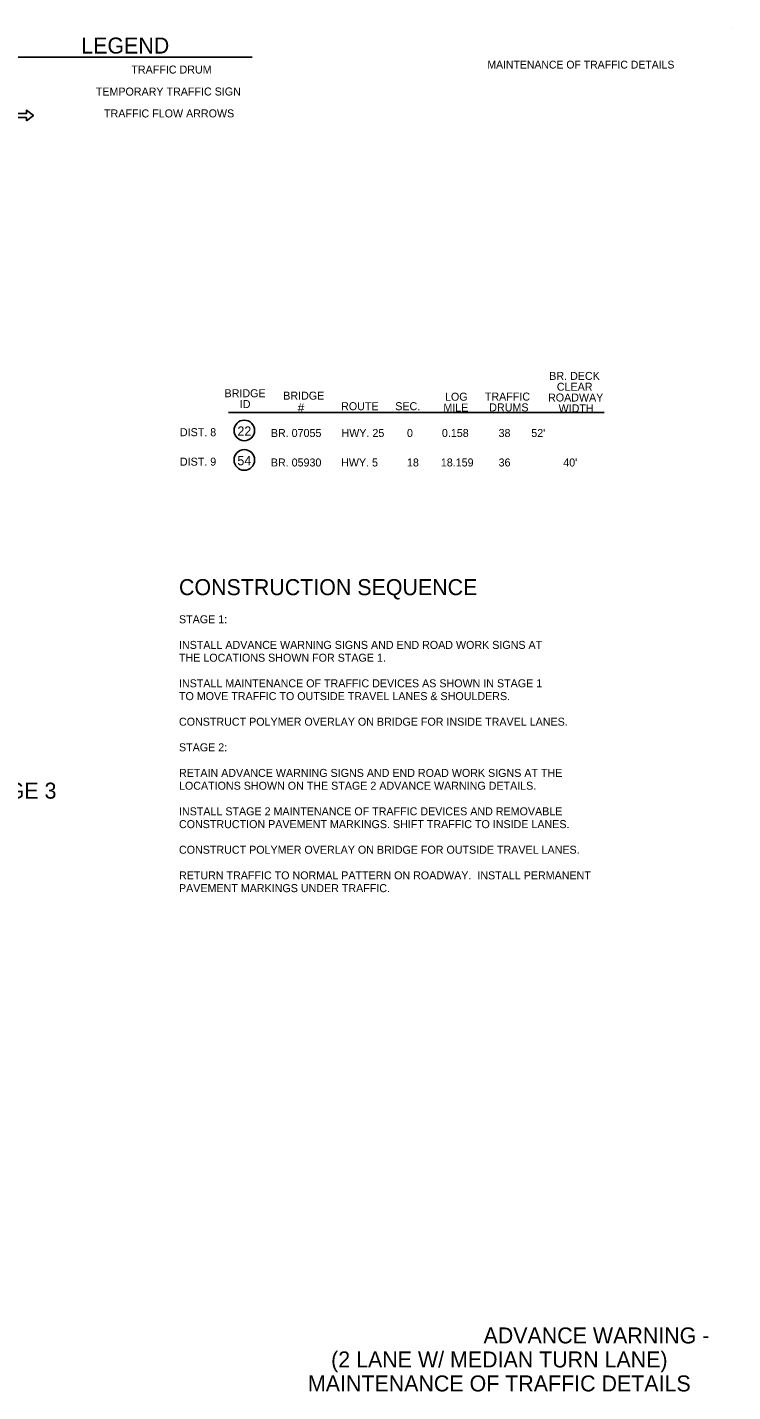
# Model space of a CAD drawing. Extents: x 1930579 to 1946213, y 596452 to 597784.
# Drawn here: x 1937455 to 1937984, y 596607 to 597630 of the extents above; entities that cross this region are included whole.
import ezdxf

# ---------------------------------------------------------------- set-up
doc = ezdxf.new("R2010")
doc.units = 0
for name, color, linetype in [('Default', 7, 'Continuous'), ('R_Border', 7, 'Continuous'), ('R_MOT', 7, 'Continuous'), ('S_AREA_CALC', 7, 'Continuous')]:
    doc.layers.add(name, color=color, linetype=linetype)

msp = doc.modelspace()

# ---------------------------------------------------------------- linework, layer by layer
at = {"layer": 'Default'}
for centre in [(1937617.7, 597327.6), (1937617.7, 597305.5)]:
    msp.add_circle(centre, 7.71, dxfattribs=at)
at = {"layer": 'R_Border'}
for p, q in [((1937429.7, 597607.5), (1937623.6, 597607.6)), ((1937605.9, 597341), (1937887.6, 597341))]:
    msp.add_line(p, q, dxfattribs=at)
at = {"layer": 'R_MOT'}
msp.add_lwpolyline([(1937454.3, 597559.7), (1937459.5, 597563.7), (1937454.3, 597567.7), (1937454.3, 597565.2), (1937439.6, 597565.2), (1937439.6, 597562.2), (1937454.3, 597562.2)], close=True, dxfattribs=at)
at = {"layer": 'S_AREA_CALC'}
msp.add_line((1937984, 597629.9), (1937984, 597629.9), dxfattribs=at)

# ---------------------------------------------------------------- texts
at = {"layer": 'Default'}
msp.add_text('MIRROR LAYOUT FOR STAGE 3', height=12, dxfattribs=at).set_placement((1937232.5, 597051.5))
at = {"layer": 'R_Border'}
for s, height, rotation, p in [('LEGEND', 12, 0.0388, (1937495.4, 597610.2)), ('TRAFFIC DRUM', 6, 0.0388, (1937533, 597595.2)), ('TEMPORARY TRAFFIC SIGN', 6, 0.0388, (1937506.3, 597578.7)), ('TRAFFIC FLOW ARROWS', 6, 0.0388, (1937512.5, 597562.3)), ('BR. DECK ', 6, 360, (1937846.4, 597365.5)), ('CLEAR', 6, 360, (1937852.1, 597357.4)), ('BRIDGE ', 6, 360, (1937602.9, 597352.5)), ('ID', 6, 360, (1937614.3, 597344.4)), ('BRIDGE ', 6, 360, (1937646.9, 597350.7)), ('LOG', 6, 360, (1937768.2, 597349.9)), ('TRAFFIC ', 6, 360, (1937798.1, 597350)), ('ROADWAY ', 6, 360, (1937845.5, 597349.3)), ('#', 6.71, 360, (1937657.7, 597341.3)), ('ROUTE', 6, 360, (1937690.3, 597342.8)), ('SEC.', 6, 360, (1937730.9, 597342.8)), ('MILE', 6, 360, (1937767, 597341.8)), ('DRUMS', 6, 360, (1937801.4, 597341.9)), ('WIDTH', 6, 360, (1937853.4, 597341.2)), ('22', 7, 360, (1937612.5, 597323.6)), ('DIST. 8', 6, 360, (1937569.4, 597323.3)), ('BR. 07055', 6, 360, (1937637.6, 597322.7)), ('HWY. 25', 6, 360, (1937690.6, 597322.7)), ('0', 6, 360, (1937739.7, 597322.7)), ('0.158', 6, 360, (1937765.9, 597322.7)), ("38       52'", 6, 360, (1937808.4, 597322.7)), ('DIST. 9', 6, 360, (1937569.4, 597301.2)), ('54', 7, 360, (1937612.5, 597301.5)), ('BR. 05930', 6, 360, (1937637.6, 597300.6)), ('HWY. 5', 6, 360, (1937690.3, 597300.6)), ('18', 6, 360, (1937739.7, 597300.6)), ('18.159', 6, 360, (1937765.1, 597300.6)), ('36      ', 6, 360, (1937808.4, 597300.6)), ("40'      ", 6, 360, (1937856.9, 597300.6)), ('CONSTRUCTION SEQUENCE', 12, 360, (1937568.7, 597204.1)), ('STAGE 1:', 6, 360, (1937568.7, 597183)), ('INSTALL ADVANCE WARNING SIGNS AND END ROAD WORK SIGNS AT', 6, 360, (1937568.7, 597163.8)), ('THE LOCATIONS SHOWN FOR STAGE 1.', 6, 360, (1937568.7, 597154.2)), ('INSTALL MAINTENANCE OF TRAFFIC DEVICES AS SHOWN IN STAGE 1', 6, 360, (1937568.7, 597135)), ('TO MOVE TRAFFIC TO OUTSIDE TRAVEL LANES & SHOULDERS.', 6, 360, (1937568.7, 597125.4)), ('CONSTRUCT POLYMER OVERLAY ON BRIDGE FOR INSIDE TRAVEL LANES.', 6, 360, (1937568.7, 597106.2)), ('STAGE 2:', 6, 360, (1937568.7, 597087)), ('RETAIN ADVANCE WARNING SIGNS AND END ROAD WORK SIGNS AT THE', 6, 360, (1937568.7, 597067.8)), ('LOCATIONS SHOWN ON THE STAGE 2 ADVANCE WARNING DETAILS.', 6, 360, (1937568.7, 597058.2)), ('INSTALL STAGE 2 MAINTENANCE OF TRAFFIC DEVICES AND REMOVABLE', 6, 360, (1937568.7, 597039)), ('CONSTRUCTION PAVEMENT MARKINGS. SHIFT TRAFFIC TO INSIDE LANES.', 6, 360, (1937568.7, 597029.4)), ('CONSTRUCT POLYMER OVERLAY ON BRIDGE FOR OUTSIDE TRAVEL LANES.', 6, 360, (1937568.7, 597010.2)), ('RETURN TRAFFIC TO NORMAL PATTERN ON ROADWAY.  INSTALL PERMANENT', 6, 360, (1937568.7, 596991)), ('PAVEMENT MARKINGS UNDER TRAFFIC.', 6, 360, (1937568.7, 596981.4)), ('ADVANCE WARNING -', 12, 360, (1937797.1, 596643)), ('(2 LANE W/ MEDIAN TURN LANE)', 12, 360, (1937682.8, 596625)), ('MAINTENANCE OF TRAFFIC DETAILS', 12, 360, (1937665.4, 596607))]:
    msp.add_text(s, height=height, rotation=rotation, dxfattribs=at).set_placement(p)
at = {"layer": 'S_AREA_CALC'}
msp.add_text('MAINTENANCE OF TRAFFIC DETAILS', height=5.862, rotation=360, dxfattribs=at).set_placement((1937800, 597599))

doc.saveas('drawing.dxf')
